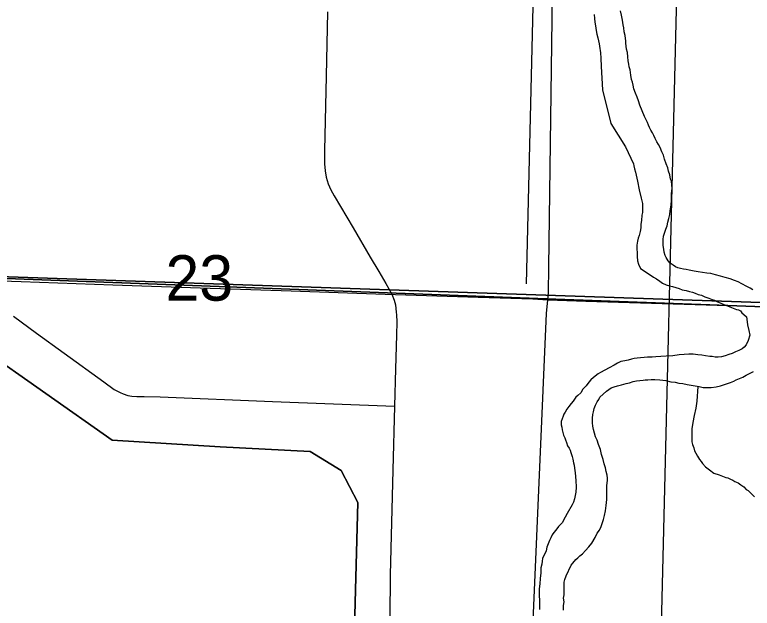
# Model space of a CAD drawing. Extents: x 0 to 68, y 0 to 52.9.
# Drawn here: x 48.575 to 49.292, y 37.512 to 38.089 of the extents above; entities that cross this region are included whole.
import ezdxf

# ---------------------------------------------------------------- set-up
doc = ezdxf.new("R2010")
doc.units = 0
for name, color, linetype in [('Default', 7, 'Continuous'), ('GM_X_Minor_Lake', 7, 'Continuous'), ('GM_X_Minor_River', 7, 'Continuous'), ('GM_X_Township', 7, 'Continuous'), ('GM_X_Township_Road', 7, 'Continuous')]:
    doc.layers.add(name, color=color, linetype=linetype)

msp = doc.modelspace()

# ---------------------------------------------------------------- linework, layer by layer
at = {"layer": 'Default'}
for points in [[(49.76395, 39.10497), (49.74566, 37.79421), (48.42638, 37.83913), (48.45764, 39.14733)], [(48.17291, 38.35564), (49.22316, 38.3205), (49.19761, 37.26933), (48.15695, 37.30357)], [(48.42638, 37.83913), (49.74566, 37.79421), (49.69961, 36.50844), (48.38433, 36.55233)]]:
    msp.add_lwpolyline(points, close=True, dxfattribs=at)
for points in [[(49.18089, 38.00529), (49.17973, 38.00892), (49.17817, 38.01296), (49.1766, 38.017), (49.17584, 38.02062), (49.17508, 38.02345), (49.17431, 38.02627), (49.17355, 38.0303), (49.17281, 38.03553), (49.17204, 38.03835), (49.17167, 38.04117), (49.17091, 38.0444), (49.17055, 38.04801), (49.1702, 38.05244), (49.16944, 38.05566), (49.16907, 38.05848), (49.1687, 38.0613), (49.16873, 38.06371), (49.16836, 38.06613), (49.168, 38.06894), (49.16724, 38.07257), (49.16688, 38.07619), (49.16611, 38.07942), (49.16536, 38.08384), (49.16462, 38.08867), (49.16346, 38.09271)], [(49.13804, 38.08943), (49.13839, 38.0854), (49.13875, 38.08178), (49.13911, 38.07816), (49.13986, 38.07373), (49.14062, 38.07011), (49.14138, 38.06648), (49.14214, 38.06366), (49.14291, 38.06084), (49.14329, 38.05842), (49.14401, 38.05198), (49.14435, 38.04675), (49.14465, 38.03871), (49.14598, 38.01619), (49.15402, 37.98354), (49.16824, 37.96085), (49.17609, 37.94428), (49.17647, 37.94226), (49.17724, 37.93944), (49.178, 37.93622), (49.1799, 37.92735), (49.18181, 37.91889), (49.18372, 37.91083), (49.18487, 37.90559), (49.18482, 37.90198), (49.18478, 37.89876), (49.18475, 37.89675), (49.18432, 37.89435), (49.18385, 37.88913), (49.1834, 37.88552), (49.18336, 37.8819), (49.18251, 37.8783), (49.18166, 37.87469), (49.18082, 37.87189), (49.17997, 37.86909), (49.17952, 37.86508), (49.17978, 37.85423), (49.18013, 37.8498), (49.1809, 37.84658), (49.18286, 37.84253), (49.18646, 37.84008), (49.19085, 37.8372), (49.19325, 37.83557), (49.19564, 37.83393), (49.19844, 37.83228), (49.20164, 37.83023), (49.20443, 37.82819), (49.20804, 37.82653), (49.21125, 37.82569), (49.21406, 37.82485), (49.21727, 37.824), (49.22048, 37.82315), (49.22329, 37.82191), (49.22731, 37.82105), (49.23052, 37.82021), (49.23333, 37.81937), (49.23614, 37.81853), (49.23894, 37.81729), (49.24216, 37.81644), (49.24536, 37.81479), (49.24937, 37.81353), (49.25258, 37.81229), (49.25499, 37.81185), (49.25779, 37.81021), (49.26019, 37.80897), (49.2634, 37.80772), (49.2666, 37.80648), (49.26981, 37.80523), (49.27302, 37.80398), (49.27622, 37.80273), (49.27823, 37.80231), (49.28024, 37.80147)], [(49.29218, 37.82181), (49.28938, 37.82345), (49.28618, 37.8251), (49.28137, 37.82758), (49.27777, 37.82963), (49.27416, 37.83089), (49.27016, 37.83255), (49.26534, 37.83381), (49.26052, 37.83508), (49.2557, 37.83635), (49.25129, 37.83762), (49.24726, 37.83807), (49.24324, 37.83853), (49.23882, 37.83939), (49.2352, 37.83984), (49.23038, 37.8407), (49.22716, 37.84155), (49.22475, 37.84198), (49.22194, 37.84242), (49.21913, 37.84326), (49.21712, 37.84409), (49.21473, 37.84573), (49.21193, 37.84778), (49.20994, 37.84981), (49.20797, 37.85305), (49.20679, 37.85508), (49.20602, 37.8583), (49.20566, 37.86112), (49.2049, 37.86474), (49.20494, 37.86796), (49.20497, 37.87077), (49.20542, 37.87398), (49.20626, 37.87678), (49.20752, 37.88078), (49.20876, 37.88398), (49.20961, 37.88759), (49.21047, 37.89119), (49.21132, 37.8948), (49.21177, 37.89841), (49.21219, 37.90041), (49.21264, 37.90402), (49.21311, 37.90924), (49.21319, 37.91526), (49.21365, 37.92008), (49.21329, 37.9237), (49.21294, 37.92732), (49.21216, 37.92934), (49.2114, 37.93337), (49.21024, 37.937), (49.20948, 37.94022), (49.20791, 37.94426), (49.20636, 37.9487), (49.2052, 37.95273), (49.20363, 37.95597), (49.20207, 37.96001), (49.2005, 37.96284), (49.19892, 37.96568), (49.19735, 37.96891), (49.19577, 37.97174), (49.1946, 37.97417), (49.19302, 37.977), (49.19184, 37.97943), (49.19066, 37.98186), (49.18989, 37.98428), (49.18831, 37.98711), (49.18674, 37.99035), (49.18245, 38.00125), (49.18089, 38.00529)], [(49.28024, 37.80147), (49.28142, 37.79945), (49.28341, 37.79782), (49.2858, 37.79538), (49.28618, 37.79336), (49.28691, 37.78773), (49.28805, 37.78209), (49.2892, 37.77765), (49.28752, 37.77245), (49.28546, 37.76846), (49.28382, 37.76607), (49.28178, 37.76449), (49.27854, 37.76292), (49.2753, 37.76136), (49.27206, 37.7598), (49.26882, 37.75903), (49.26518, 37.75747), (49.26154, 37.75672), (49.25832, 37.75636), (49.2555, 37.7564), (49.25268, 37.75684), (49.25027, 37.75687), (49.24625, 37.75772), (49.24263, 37.75817), (49.2386, 37.75863), (49.23418, 37.75909), (49.22975, 37.75915), (49.22531, 37.7588), (49.22047, 37.75846), (49.21442, 37.75774), (49.20797, 37.75742), (49.20273, 37.75709), (49.19789, 37.75675), (49.19426, 37.7564), (49.18983, 37.75646), (49.1866, 37.7561), (49.18297, 37.75574), (49.17975, 37.75538), (49.17692, 37.75502), (49.17409, 37.75425), (49.17086, 37.75349), (49.16763, 37.75273), (49.16399, 37.75197), (49.16075, 37.75041), (49.1575, 37.74844), (49.15264, 37.7461), (49.14412, 37.74139), (49.14169, 37.74021), (49.13721, 37.73666), (49.13476, 37.73428), (49.13272, 37.73189), (49.13025, 37.72831), (49.12699, 37.72514), (49.12493, 37.72155), (49.12208, 37.71918), (49.12005, 37.71759), (49.11758, 37.71361), (49.11554, 37.71123), (49.11349, 37.70844), (49.11144, 37.70565), (49.10979, 37.70286), (49.10856, 37.70087), (49.10773, 37.69887), (49.10689, 37.69647), (49.10605, 37.69367), (49.10601, 37.69046), (49.10639, 37.68844), (49.10675, 37.68563), (49.10753, 37.68321), (49.1083, 37.68038), (49.10948, 37.67796), (49.11026, 37.67594), (49.11103, 37.67351), (49.1122, 37.67029), (49.11378, 37.66785), (49.11456, 37.66583), (49.11534, 37.66382), (49.1165, 37.65978), (49.11727, 37.65736), (49.11803, 37.65373), (49.11841, 37.65132), (49.11877, 37.6485), (49.11952, 37.64407), (49.12023, 37.63643), (49.12055, 37.62999), (49.12009, 37.62518), (49.11965, 37.62197), (49.1188, 37.61877), (49.11795, 37.61557), (49.11671, 37.61277), (49.11177, 37.6044), (49.10971, 37.60081), (49.10682, 37.59522), (49.10315, 37.59165), (49.10069, 37.58807), (49.09865, 37.58609), (49.09701, 37.5837), (49.09576, 37.5809), (49.09452, 37.5781), (49.09327, 37.57491), (49.09202, 37.57171)], [(49.10817, 37.51042), (49.10822, 37.51484), (49.10867, 37.51845), (49.10831, 37.52207), (49.10876, 37.52528), (49.1088, 37.5289), (49.10884, 37.53211), (49.10888, 37.53492), (49.10891, 37.53773), (49.10935, 37.54014), (49.1106, 37.54374), (49.11557, 37.55412), (49.1172, 37.55611), (49.12007, 37.55969), (49.1221, 37.56127), (49.12414, 37.56325), (49.12659, 37.56523), (49.12944, 37.5684), (49.13271, 37.57198), (49.13558, 37.57555), (49.13887, 37.58114), (49.14094, 37.58513), (49.14299, 37.58832), (49.14465, 37.59191), (49.1459, 37.59551), (49.14715, 37.59871), (49.148, 37.60231), (49.14887, 37.60712), (49.14974, 37.61233), (49.15021, 37.61795), (49.15029, 37.62438), (49.15038, 37.63121), (49.15086, 37.63683), (49.15088, 37.63884), (49.15051, 37.64166), (49.14975, 37.64528), (49.14899, 37.64891), (49.14783, 37.65254), (49.14668, 37.65697), (49.14513, 37.66182), (49.14398, 37.66665), (49.14203, 37.6715), (49.14087, 37.67553), (49.1393, 37.67877), (49.13813, 37.6824), (49.13737, 37.68603), (49.13661, 37.68925), (49.13625, 37.69247), (49.1363, 37.69689), (49.13675, 37.7005), (49.13719, 37.70331), (49.13804, 37.70651), (49.13929, 37.70971), (49.14094, 37.7129), (49.14258, 37.71529), (49.14341, 37.71729), (49.14667, 37.72046), (49.14993, 37.72323), (49.1544, 37.72638), (49.15724, 37.72755), (49.16047, 37.72831), (49.16451, 37.72947), (49.16896, 37.73061), (49.17219, 37.73137), (49.17583, 37.73253), (49.17906, 37.73329), (49.18229, 37.73365), (49.18552, 37.73401), (49.18754, 37.73439), (49.18996, 37.73436), (49.19318, 37.73471), (49.19681, 37.73467), (49.20164, 37.7342), (49.20767, 37.73372), (49.21249, 37.73245), (49.21651, 37.732), (49.22013, 37.73115), (49.22415, 37.73069), (49.22817, 37.72984), (49.23219, 37.72898), (49.23621, 37.72852), (49.23982, 37.72767), (49.24384, 37.72682), (49.24747, 37.72677), (49.2515, 37.72672), (49.25634, 37.72746), (49.26079, 37.7286), (49.26564, 37.73015), (49.27049, 37.73169), (49.27373, 37.73285), (49.27576, 37.73443), (49.279, 37.7356), (49.28224, 37.73676), (49.28549, 37.73873)], [(49.28549, 37.73873), (49.28873, 37.74029), (49.29278, 37.74224)], [(49.09202, 37.57171), (49.09117, 37.5681), (49.08992, 37.56531), (49.08869, 37.56291), (49.08785, 37.56051), (49.08742, 37.55811), (49.08698, 37.5553), (49.08613, 37.55169), (49.08607, 37.54687), (49.08559, 37.54126), (49.08512, 37.53604), (49.08466, 37.53122), (49.08461, 37.52721), (49.08458, 37.52479), (49.08492, 37.51997), (49.08487, 37.51595), (49.08481, 37.51113)]]:
    msp.add_lwpolyline(points, dxfattribs=at)
at = {"layer": 'GM_X_Minor_Lake'}
for points in [[(48.31619, 36.90971), (48.35102, 36.92371), (48.8029, 36.91254), (48.84987, 36.89946), (48.8909, 36.95839), (48.90846, 37.61511), (48.89233, 37.64626), (48.86195, 37.66474), (48.77458, 37.6691), (48.66992, 37.67571), (48.54053, 37.76621), (47.86798, 37.7851), (47.84162, 37.77098)], [(47.84162, 37.77098), (47.86798, 37.7851), (48.54053, 37.76621), (48.66992, 37.67571), (48.77458, 37.6691), (48.86195, 37.66474), (48.89233, 37.64626), (48.90846, 37.61511), (48.8909, 36.95839)]]:
    msp.add_lwpolyline(points, dxfattribs=at)
at = {"layer": 'GM_X_Minor_River'}
for points in [[(48.66543, 38.48504), (48.6647, 38.46469), (49.08728, 38.4612), (49.0718, 37.82754)], [(49.2386, 37.72796), (49.23763, 37.71364), (49.23674, 37.70682), (49.23504, 37.69961), (49.23375, 37.69279), (49.23286, 37.68678), (49.23279, 37.68116), (49.23274, 37.67674), (49.2327, 37.67392), (49.23348, 37.6715), (49.23464, 37.66827), (49.23541, 37.66545), (49.23659, 37.66302), (49.23817, 37.66019), (49.24014, 37.65695), (49.24173, 37.65492), (49.24331, 37.65289), (49.24609, 37.64964), (49.25008, 37.64677), (49.25407, 37.64351), (49.25929, 37.64183), (49.26249, 37.64059), (49.2657, 37.63934), (49.26771, 37.63891), (49.27051, 37.63767), (49.27252, 37.63684), (49.27452, 37.63561), (49.27773, 37.63436), (49.28052, 37.63231), (49.28331, 37.63027), (49.2857, 37.62782), (49.2877, 37.62659), (49.29128, 37.62293), (49.29366, 37.62049)]]:
    msp.add_lwpolyline(points, dxfattribs=at)
at = {"layer": 'GM_X_Township'}
for points in [[(50.34506, 37.77433), (49.87003, 37.78728), (49.7424, 37.78907), (49.09193, 37.81286), (48.42924, 37.83782), (47.97584, 37.8521), (47.09341, 37.87493), (46.43542, 37.88698), (45.78152, 37.90751), (45.76356, 37.9078), (44.77759, 37.93161), (44.12143, 37.94309), (43.3203, 37.94792), (43.31455, 37.9477), (43.13228, 37.95106), (43.13722, 38.12535), (43.1394, 38.18651), (43.13947, 38.19396), (43.15039, 38.61621), (43.15805, 38.89613)], [(44.77759, 37.93161), (45.76356, 37.9078), (45.78152, 37.90751), (46.43542, 37.88698), (47.09341, 37.87493), (47.97584, 37.8521), (48.42924, 37.83782), (49.09193, 37.81286), (49.7424, 37.78907), (49.71566, 36.99716), (49.70773, 36.74798), (49.69511, 36.18054), (49.68722, 35.85214), (49.65449, 34.5254), (49.63258, 33.86577), (49.61888, 33.2067), (49.60976, 32.7683)]]:
    msp.add_lwpolyline(points, dxfattribs=at)
at = {"layer": 'GM_X_Township_Road'}
for points in [[(49.09285, 37.81198), (49.0935, 37.8192), (49.09404, 37.8438), (49.09925, 38.22963), (49.10317, 38.5293), (49.10319, 38.60319), (49.10607, 38.74274), (49.10674, 38.7674), (49.10875, 38.77949), (49.11151, 38.78717), (49.11544, 38.79436), (49.12489, 38.80782), (49.12863, 38.81506), (49.131, 38.82286), (49.13247, 38.8351), (49.13415, 39.12245), (49.13419, 39.12899)], [(48.87887, 38.0918), (48.87775, 38.02945), (48.87609, 37.95724), (48.87616, 37.9441), (48.87663, 37.93755), (48.87772, 37.9311), (48.87961, 37.92484), (48.88225, 37.91884), (48.88538, 37.91305), (48.90385, 37.88201), (48.92037, 37.85365), (48.9287, 37.83947), (48.93568, 37.82792), (48.94148, 37.81749), (48.94381, 37.81169), (48.94497, 37.80706), (48.94574, 37.80011), (48.94589, 37.79737), (48.94614, 37.79081), (48.94591, 37.77768), (48.94488, 37.74486), (48.94408, 37.70876)], [(48.43041, 37.8352), (48.48788, 37.83306), (48.58128, 37.82991), (48.67041, 37.82675), (48.75527, 37.82358), (48.84355, 37.82064), (48.93481, 37.81769), (49.02522, 37.81474), (49.07828, 37.81286), (49.09285, 37.81198)], [(49.06457, 37.2215), (49.07887, 37.50764), (49.09167, 37.79881), (49.09285, 37.81198)], [(49.09285, 37.81198), (49.12987, 37.81064), (49.22543, 37.80798), (49.31106, 37.80532), (49.42769, 37.80145), (49.48379, 37.79976), (49.56393, 37.7964), (49.74971, 37.78981)], [(48.574, 37.79608), (48.59642, 37.77948), (48.62309, 37.76016), (48.66174, 37.73236), (48.67165, 37.7249), (48.67742, 37.72184), (48.68043, 37.7206), (48.68498, 37.71921), (48.68902, 37.71849), (48.69361, 37.71822), (48.70078, 37.71808), (48.71623, 37.7177), (48.8256, 37.7131), (48.94408, 37.70876)], [(48.94408, 37.70876), (48.94252, 37.64655), (48.93972, 37.54475), (48.93901, 37.46162), (48.93736, 37.38041), (48.93553, 37.33454), (48.93469, 37.3115), (48.93408, 37.29179), (48.93426, 37.28853), (48.93494, 37.28538), (48.9365, 37.28244), (48.94087, 37.27933), (48.94541, 37.27858), (49.0922, 37.27388)]]:
    msp.add_lwpolyline(points, dxfattribs=at)

# ---------------------------------------------------------------- texts
at = {"layer": 'Default'}
msp.add_text('23', height=0.0442, rotation=0.00001, dxfattribs=at).set_placement((48.72152, 37.8112))

doc.saveas('drawing.dxf')
